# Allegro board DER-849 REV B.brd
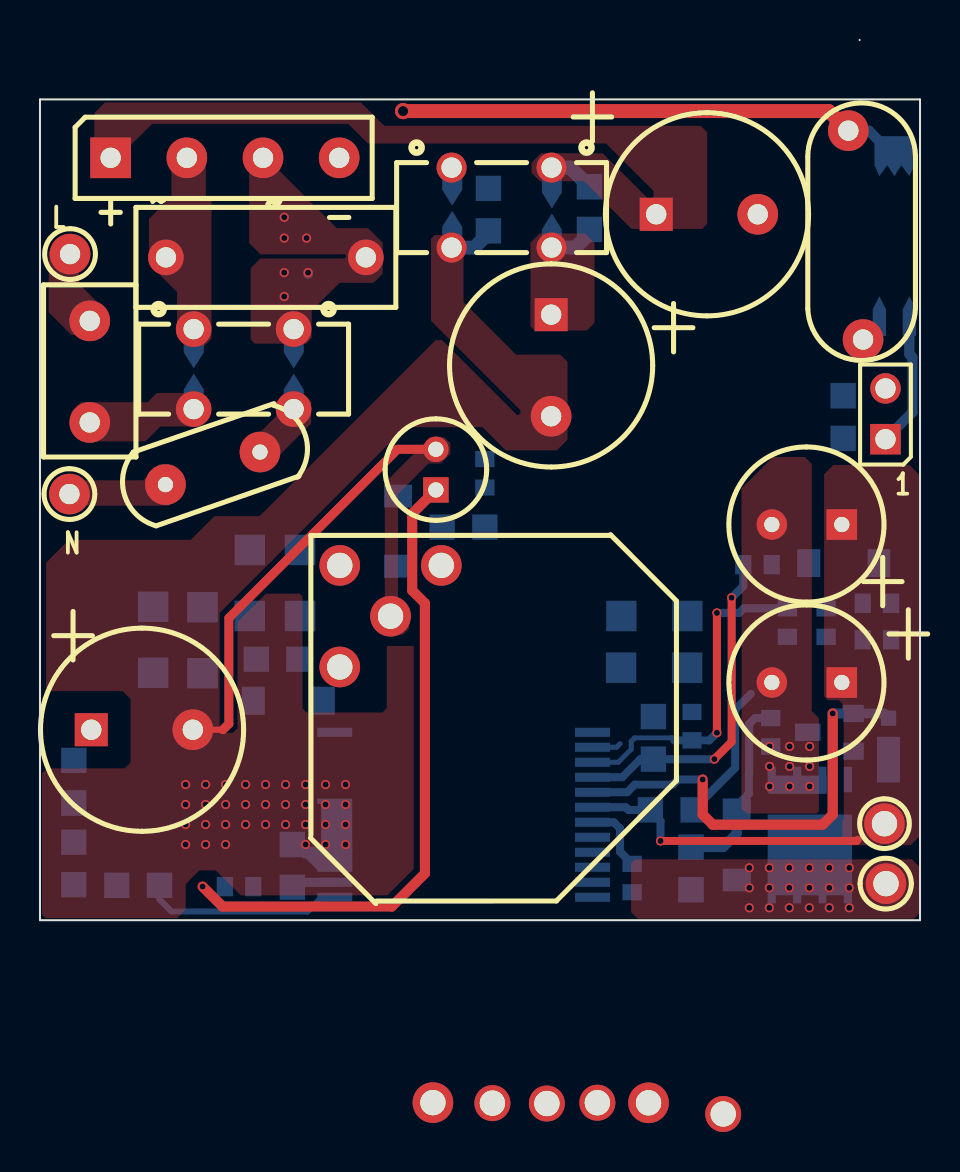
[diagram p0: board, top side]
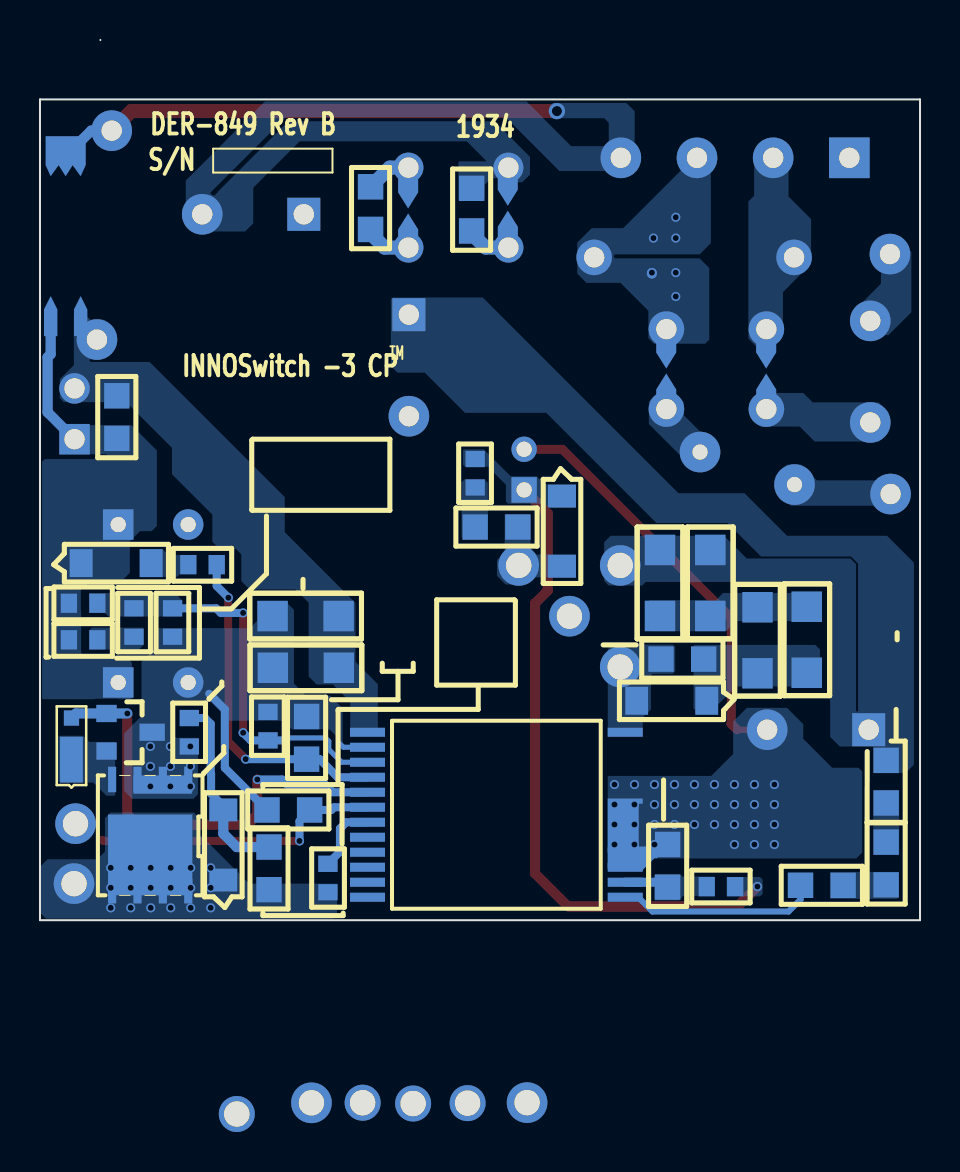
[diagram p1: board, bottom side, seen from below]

Outline 44.02 x 44.02 mm; copper layers: TOP, BOTTOM. Coordinates in mm from the lower left corner of the outline.
Outline path: 0,41.05 44.02,41.05 44.02,0 0,0 0,41.05

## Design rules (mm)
constraint set DEFAULT: min track width 0.508

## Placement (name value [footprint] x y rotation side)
BR1  KBP306G-BP  [PIDAXBRIDGEKBP306G]  3.54 38.13 0 top
C1  18 uf  [PIPOLCAPCYLD400LS200040]  30.82 35.3 0 top
C2  18 uf  [PIPOLCAPCYLD400LS200040]  25.57 30.28 270 top
C3  18 uf  [PIPOLCAPCYLD400LS200040]  2.57 9.53 0 top
C4  0.1 uF  [PINPXCAPRAD5X13X11P1MM040]  6.3 33.15 0 top
C5  2.2 nF  [PISMC1206]  13 18.52 270 bottom
C6  1 uF  [PISMC0805]  12.62 1.65 90 bottom
C7  100 pF  [PISMC0603]  22.25 23.06 270 bottom
C8  10 uF  [PIPOLCAPCLYD200LS80030]  19.8 21.52 90 top
C9  1 nF  [PISMC0603]  36.55 10.11 270 bottom
C10  2.2 uF  [PISMC0805]  30.68 10.19 270 bottom
C11  330 uF  [PIPOLCAPCYLD315LS138D030]  40.11 19.79 180 top
C12  330 uF  [PIPOLCAPCYLD315LS138D030]  40.11 11.89 180 top
C13  2.2 uF  [PISMC0805]  40.18 24.09 90 bottom
C14  330 pF  [PISMC0603]  32.61 10.41 270 bottom
C15  1 nF  [PINPYCAPRAD540X290LS400040]  42.93 39.04 260 top
C16  2.2 uF  [PISMC0805]  32.66 5.51 180 bottom
C17  47 pF  [PISMC0805]  10.82 13.06 0 bottom
C18  47 nF  [PISMC0603]  42.57 14.02 180 bottom
D1  S1ML  [PI_SM_SOD-123_12]  10.67 10.97 0 bottom
D2  S1ML  [PI_SM_SOD-123_12]  17.91 21.21 270 bottom
D3  S1ML  [PI_SM_SOD-123_12]  34.85 2.01 90 bottom
D5  PD3S140-7  [PISMD_POWERDI323]  42.44 8.03 270 bottom
F1  3.15 A  [PI_RST_MICROFUSE]  2.49 29.97 270 top
FL1  Hole_50mils  [PI_HOLE_50MIL]  42.24 4.83 0 top
FL2  Hole_50mils  [PI_HOLE_50MIL]  42.32 1.83 90 top
J1  OUTPUT  [PI_MOLEX_2_100_HEADER]  42.29 24.05 90 top
L1  700 uH  [PI_4P_10XD4MMD40]  10.19 27.56 90 top
L2  5000 uH  [PI_4P_10XD4MMD40]  23.09 35.64 90 top
NOREF  -  []  0 41.05 0 top
NOREF#2  -  []  -150.78 54.23 0 top
NOREF#3  -  []  0 0 90 top
NOREF#4  -  []  -228.6 -144.78 0 top
Q1  TSM160N10LCR  [PISMPQFN5X6B]  36.6 7.04 0 bottom
Q4  AO3415A  [PISMSOT23123_1]  40.69 8.46 270 bottom
R1  20  [PISMR1206]  5.66 15.68 270 bottom
R2  240 k  [PISMR1206]  10.49 18.52 270 bottom
R3  10  [PISMR0805]  22.25 19.66 180 bottom
R4  6.2 k  [PISMR0603]  9.25 1.68 0 bottom
R5  100  [PISMR0603]  36.6 17.78 180 bottom
R6  47  [PISMR0603]  29.62 1.4 90 bottom
R7  10  [PISMR0805]  32.56 1.52 90 bottom
R8  0.025  [PISMR1206]  32.37 12.62 180 bottom
R9  1.2 M  [PISMR0805]  1.69 7.99 270 bottom
R10  1.2 M  [PISMR0805]  1.69 3.9 270 bottom
R11  1.2 M  [PISMR0805]  3.84 1.74 0 bottom
R12  100 k  [PISMR0603]  42.57 15.85 180 bottom
R13  7.5 k  [PISMR0603]  37.39 15.6 270 bottom
R14  0.025  [PISMR1206]  32.38 15.21 180 bottom
R15  4.7 k  [PISMR0805]  27.48 36.68 270 bottom
R16  4.7 k  [PISMR0805]  22.43 36.6 270 bottom
R17  20  [PISMR1206]  8.13 15.65 270 bottom
R18  10.0K  [PISMR0603]  39.32 14.17 90 bottom
RT1  2.5  [PI_RAD150X300LS200D030]  11 23.41 199 top
SG1  6.0mm gap  [PI_SPARK_GAP_6P5MM_3P]  42.73 34.46 270 bottom
T1  RM7/I  [PI_BOBBIN_RM7_8P_CLP]  30.23 7.58 180 top
TP1  N  [PITPKEYSTONE100X100]  1.47 21.31 0 top
TP2  L  [PITPKEYSTONE100X100]  1.5 33.31 0 top
U1  INN3267C-H205  [PI_IC_INSOP_24D]  27.64 9.4 180 bottom
VR1  MMSZ5248B-7-F  [PI_SM_SOD-123_12]  41.96 17.86 180 bottom

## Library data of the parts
BR1 = DISCRETE BRIDGE_+~~-
C1-C3 = CAP POL: alternate symbols: (pipolcapclyd395x630ls200030h)
C4 = CAP NP: alternate symbols: (pinpxcaprad5x13x11p1mm040h)
C5-C7 C9 C10 C13 C16-C18 = CAP NP
C8 = CAP POL: alternate symbols: (pipolcapclyd200ls80030h)
C11 C12 = CAP POL: alternate symbols: (pipolcapcyld315ls138d030h)
C14 = CAP NP: alternate symbols: (pismc0603_1)
C15 = CAP NP: alternate symbols: (pinpycaprad540x290ls400040h,pinpycaprad500x220ls400040)
D1-D3 D5 = DIODE
F1 = FUSE: alternate symbols: (pirstmicrofusehoz)
FL1 FL2 = FlyingLead
J1 = CON2
L1 L2 = TORRID 4P_21_34
Q1 = FET_N_SGD_123_4_5678
Q4 = FET_P_GSD
R1-R5 R7-R18 = R
R6 = R: alternate symbols: (pismr0603_1)
RT1 = THERMISTOR: alternate symbols: (pirad400x300ls200040_h)
SG1 = SPARK_GAP_3p
T1 = BRM7_8P_CLP_2
TP1 TP2 = TESTPOINT
U1 = Inno3CP
VR1 = DIODE_ZENER

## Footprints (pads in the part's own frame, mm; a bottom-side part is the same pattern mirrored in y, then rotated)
PI_4P_10XD4MMD40
  round 1.5 hole 1.016: 1(-2,2.5) 2(2,2.5) 3(2,-2.5) 4(-2,-2.5)
PI_BOBBIN_RM7_8P_CLP
  round 1.8 hole 1.27: 1(2.355,16.71) 6(7.605,16.73) 7(-3.94,17.275) 8(4.88,16.75)
  round 2.032 hole 1.27: 2(10.16,-10.16) 3(12.7,-7.62) 4(15.24,-10.16) 5(15.24,-5.08) CLP1(-0.205,16.715) CLP2(10.58,16.705)
PI_HOLE_50MIL
  round 2.032 hole 1.27: 1(0,0)
PI_IC_INSOP_24D
  rect 1.75x0.45 smd: 1(0,0) 2(0,-0.75) 3(0,-1.5) 4(0,-2.25) 5(0,-3) 6(0,-3.75) 7(0,-4.5) 8(0,-5.25) 9(0,-6) 10(0,-6.75) 11(0,-7.5) 12(0,-8.25) 13(12.89,-8.25) 14(12.89,-7.5) 15(12.89,-6.75) 24(12.89,0)
  custom 0.438x0.438 smd: 16(12.89,-4.67)
PI_MOLEX_2_100_HEADER
  rect 1.524x1.524 hole 1.016: 1(0,0)
  round 1.524 hole 1.016: 2(2.54,0)
PI_RAD150X300LS200D030
  round 2.032 hole 0.762: 1(0,0) 2(5,0)
PI_RST_MICROFUSE
  round 2.032 hole 1.016: 1(0,0) 2(5.08,0)
PI_SM_SOD-123_12
  rect 1.143x1.397 smd: 1(0,0) 2(3.505,0)
PI_SPARK_GAP_6P5MM_3P
  custom 0.5x0.5 smd: 1(-3.75,0)
  custom 0.167x0.167 smd: 2(4.25,0.75) 3(4.25,-0.75)
PIDAXBRIDGEKBP306G
  rect 2.032x2.032 hole 1.016: 1(0,0)
  round 2.032 hole 1.016: 2(3.81,0) 3(7.62,0) 4(11.43,0)
PINPXCAPRAD5X13X11P1MM040
  round 1.778 hole 1.016: 1(0,0) 2(10,0)
PINPYCAPRAD540X290LS400040
  round 2.032 hole 1.016: 1(0,-2.54) 2(10.16,0)
PIPOLCAPCLYD200LS80030
  rect 1.27x1.27 hole 0.762: 1(0,0)
  round 1.27 hole 0.762: 2(2.032,0)
PIPOLCAPCYLD315LS138D030
  rect 1.524x1.524 hole 0.762: 1(0,0)
  round 1.524 hole 0.762: 2(3.5,0)
PIPOLCAPCYLD400LS200040
  rect 1.651x1.651 hole 1.016: 1(0,0)
  round 2.032 hole 1.016: 2(5.08,0)
PISMC0603
  rect 0.813x0.965 smd: 1(0,0) 2(1.422,0)
PISMC0805
  rect 1.27x1.27 smd: 1(0,0) 2(2.134,0)
PISMC1206
  rect 1.524x1.524 smd: 1(0,0) 2(3.302,0)
PISMD_POWERDI323
  rect 2.286x1.143 smd: 1(0,0)
  rect 0.762x0.762 smd: 2(-2.083,0)
PISMPQFN5X6B
  rect 0.406x1.27 smd: 1(0,0) 2(1.27,0) 3(2.54,0) 4(3.81,0)
  rect 0.406x1.219 smd: 5(3.81,5.588) 6(2.54,5.588) 7(1.27,5.588) 8(0,5.588)
PISMR0603
  rect 0.813x0.965 smd: 1(0,0) 2(1.422,0)
PISMR0805
  rect 1.27x1.27 smd: 1(0,0) 2(2.134,0)
PISMR1206
  rect 1.524x1.524 smd: 1(0,0) 2(3.302,0)
PISMSOT23123_1
  rect 0.864x1.016 smd: 1(-1.88,0) 2(0,0)
  rect 0.864x1.27 smd: 3(-0.94,2.286)
PITPKEYSTONE100X100
  round 2.032 hole 1.016: 1(0,0)

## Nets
18V, 1.67A: C11.1 C12.1 C13.1 C16.2 C18.1 FL1.1 J1.1 R12.1 SG1.3 U1.6 VR1.1
NC8: U1.8
NC9: U1.9
NC10: U1.10
NC11: U1.11
NC12: U1.12
NC15: U1.15
RTN: C13.2 C15.2 J1.2 R8.2 R14.2 SG1.2 U1.1
N12273366: F1.2 L1.1
N12273454: BR1.1 C1.1 L2.3 R15.1
N12273677: BR1.4 C1.2 C15.1 L2.2 R16.1 SG1.1
N12273859: C2.1 C3.1 C5.1 L2.4 R2.1 R9.1 R15.2 T1.4
N12273903: C2.2 C3.2 C6.2 C8.2 L2.1 R16.2 T1.3 U1.16
N12275039: C5.2 R1.1 R2.2 R17.1
N12275267: C6.1 R4.2 U1.14
N12275350: D2.2 R3.2 T1.2
N12275682: C7.2 R3.1
N12275686: C7.1 C8.1 D2.1 R4.1
N12279930: R6.2 U1.7
N12279938: D3.1 FL2.1 Q1.5 Q1.6 Q1.7 Q1.8 R6.1 R7.1
N12280045: C9.2 C10.1 C11.2 C12.2 C14.1 C16.1 Q1.1 Q1.2 Q1.3(S3) Q4.3 R8.1 R13.2 R14.1 U1.2
N12283028: R11.2 U1.13(VPIN)
N12284778: C14.2 R12.2 R13.1 R18.2 U1.3
N12285860: L1.4 RT1.1
N12290600: C9.1 D3.2 R7.2
N12292662: D5.1 Q1.4 Q4.2(S)
N12292685: D5.2 Q4.1 U1.5
N12293491: C10.2 R5.2 U1.4
N12296994: R5.1 VR1.2
N12297940: BR1.3(AC2) C4.2 L1.3
N12297952: BR1.2 C4.1 L1.2
N12298342: C17.1 D1.1 R1.2 R17.2
N12298360: C17.2 D1.2 T1.5 U1.24
N12331858: R9.2 R10.1
N12331878: R10.2 R11.1
N12332729: F1.1 TP2.1
N12332733: RT1.2 TP1.1
N123253661: C18.2 R18.1

Pads without a net: T1 1 6 7 8 CLP1 CLP2

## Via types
v1: diameter 0.457, hole 0.305, TOP to BOTTOM, 74 vias
v2: diameter 0.813, hole 0.508, TOP to BOTTOM, 1 via

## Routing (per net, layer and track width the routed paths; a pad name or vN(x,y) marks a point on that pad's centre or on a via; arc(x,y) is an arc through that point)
18V, 1.67A: length 21.4
  TOP w0.4: 40.89,4.01 40.84,3.96 v1(31.04,3.96)
  BOTTOM w0.4: v1(31.04,3.96) 31.04,4.95 30.53,5.46 C16.2 29.44,5.51 29.31,5.65 U1.6
  BOTTOM w0.508: J1.1 43.64,25.4 43.64,28.15 43.48,28.31 SG1.3
N12273454: length 2.3
  BOTTOM w0.7: R15.1 26.52,37.64 L2.3
N12273677: length 25.5
  TOP w0.7: C15.1 39.45,40.46 v2(18.16,40.46)
  BOTTOM w0.508: C15.1 41.46,39.48 SG1.1
N12273859: length 2.4
  BOTTOM w0.7: L2.4 26.78,33.64 27.48,34.34 R15.2
N12273903: length 23.3
  TOP w0.3: C3.2 9.15,9.53
  TOP w0.45: C8.2 17.89,23.55 9.45,15.11 9.45,9.82 9.15,9.53
  BOTTOM w0.7: R16.2 22.43,34.34 21.73,33.64 L2.1
  vias: v1(7.28,6.78) v1(7.28,5.78) v1(7.28,4.78) v1(7.28,3.78) v1(8.28,6.78) v1(8.28,5.78) v1(8.28,4.78) v1(8.28,3.78) v1(9.28,6.78) v1(9.28,5.78) v1(9.28,4.78) v1(9.28,3.78) v1(10.28,6.78) v1(10.28,5.78) v1(10.28,4.78) v1(11.28,6.78) v1(11.28,5.78) v1(11.28,4.78) v1(12.28,6.78) v1(12.28,5.78) v1(12.28,4.78) v1(13.28,6.78) v1(13.28,5.78) v1(13.28,4.78) v1(13.28,3.78) v1(14.28,6.78) v1(14.28,5.78) v1(14.28,4.78) v1(14.28,3.78) v1(15.28,6.78) v1(15.28,5.78) v1(15.28,4.78) v1(15.28,3.78)
N12275267: length 2.2
  BOTTOM w0.45: U1.14 12.87,1.9 C6.1
N12275686: length 32.2
  TOP w0.504: v1(8.13,1.68) 9.13,0.69 17.6,0.69 19.25,2.34 19.25,15.85 18.62,16.48 18.62,20.33 C8.1
N12279930: length 3.5
  BOTTOM w0.4: U1.7 28.7,4.9 29.02,4.58 29.02,3.42 R6.2
N12279938:
  vias: v1(35.48,2.62) v1(35.48,1.62) v1(35.48,0.62) v1(36.48,2.62) v1(36.48,1.62) v1(36.48,0.62) v1(37.48,2.62) v1(37.48,1.62) v1(37.48,0.62) v1(38.48,2.62) v1(38.48,1.62) v1(38.48,0.62) v1(39.48,2.62) v1(39.48,1.62) v1(39.48,0.62) v1(40.48,2.62) v1(40.48,1.62) v1(40.48,0.62)
N12280045: length 8.5
  BOTTOM w0.25: U1.2 28.84,8.65 29.02,8.82
  BOTTOM w0.4: C16.1 34.77,7.62 34.77,10.54 35.55,11.32
  vias: v1(36.5,8.69) v1(36.5,7.69) v1(36.5,6.69) v1(37.5,8.69) v1(37.5,7.69) v1(37.5,6.69) v1(38.5,8.69) v1(38.5,7.69) v1(38.5,6.69)
N12283028: length 10
  BOTTOM w0.3: R11.2 5.98,1.03 6.58,0.43 13.38,0.43 14.1,1.15 U1.13
N12284778: length 16.8
  TOP w0.4: v1(33.86,9.37) v1(33.86,15.37)
  BOTTOM w0.25: 31.73,8.99 31.6,9.12 29.74,9.12 29.57,8.95 29.57,8.54 28.93,7.9 U1.3
  BOTTOM w0.4: R13.1 35.2,15.6 34.98,15.37 v1(33.86,15.37) ; 31.73,8.99 C14.2 33.48,8.99 v1(33.86,9.37)
N12290600: length 9.5
  BOTTOM w0.4: D3.2 34.85,5.71 35.46,6.32 35.46,7.31 35.48,7.33 35.48,9.82 35.77,10.11 C9.1
  BOTTOM w0.508: R7.2 34.18,3.66 34.85,4.33 D3.2
N12292685: length 22.4
  TOP w0.508: v1(39.65,10.34) 39.65,5.28 39.14,4.78 33.66,4.78 33.15,5.28 v1(33.15,7.04)
  BOTTOM w0.4: v1(33.15,7.04) 31.91,7.04 31.65,6.78 29.76,6.78 29.37,6.4 U1.5
  BOTTOM w0.508: D5.2 42.21,10.34 Q4.1 v1(39.65,10.34)
N12293491: length 16.8
  TOP w0.4: v1(33.73,8.05) 34.59,8.92 v1(34.59,16.13)
  BOTTOM w0.4: v1(34.59,16.13) 35.18,16.71 35.18,17.78 ; U1.4 29.13,7.15 30.03,8.05 C10.2 v1(33.73,8.05)
N12297940: length 0
  BOTTOM w0.508: 13.41,32.33 13.41,32.36
  vias: v1(12.22,35.15) v1(12.22,34.11) v1(12.22,32.38) v1(12.22,31.19) v1(13.34,34.11) v1(13.41,32.38)

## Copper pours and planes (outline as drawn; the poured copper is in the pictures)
18V, 1.67A on TOP: 40.13,10.82 39.95,11 39.42,11 39.22,11.2 39.22,22.3 39.69,22.77 43.49,22.77 43.97,22.29 43.97,4.17 43.55,3.75 40.4,3.75 40.13,4.01
18V, 1.67A on BOTTOM: 39.42,11.1 39.42,12.88 39.71,13.17 41.77,13.17 41.96,13.36 41.96,15.47 41.97,15.48 41.97,16.5 41.43,17.04 39.85,17.04 39.52,17.37 39.52,18.95 39.01,19.46 38.43,19.46 38.18,19.71 38.18,23.5 39.44,24.75 42.98,24.75 42.98,23.55 42.74,23.31 42.73,23.3 40.69,23.3 40.62,23.23 40.62,23.12 40.69,23.06 43.79,23.06 43.91,22.93 43.91,11.07 43.89,11.05 39.47,11.05
RTN on BOTTOM: 33.95,16.95 33.95,18.3 34.34,18.69 35.17,18.69 35.4,18.92 35.4,20.28 37.41,22.3 37.41,23.62 37.82,24.03 37.83,24.03 37.83,24.04 39.7,25.91 42.82,25.91 43.03,26.11 43.03,27.05 42.32,27.76 42.32,30.37 42.27,30.43 41.89,30.43 41.49,30.03 40.79,30.03 40.28,29.51 40.28,28.57 40.77,28.09 41.45,28.09 41.55,27.99 41.48,27.91 38.53,27.91 31.78,21.16 31.78,19.41 28.23,15.86 28.23,12.92 27.12,11.8 27.12,9.25 28.35,9.25 28.5,9.4 28.5,10.92 29.36,11.79 30.18,11.79 30.58,12.19 30.58,15.88 31.23,16.53 33.53,16.53
N12273366 on BOTTOM (solid shape): 8.19,26.54 8.19,25.33 8.11,25.24 7.19,25.24 7.19,26.54 7.69,27.34
N12273366 on TOP: 5.28,23.95 6.02,24.69 7.98,24.69 8.43,25.15 8.43,25.98 8.05,26.37 5.84,26.37 5.38,25.91 2.06,25.91 1.59,25.44 1.59,24.41 2.05,23.95
N12273366 on BOTTOM: 5.27,23.94 6.02,24.69 7.98,24.69 8.43,25.15 8.43,25.98 8.05,26.37 5.84,26.37 5.37,25.9 2.07,25.9 1.57,25.4 1.57,24.41 2.04,23.94
N12273454 on BOTTOM (solid shape): 26.1,36.4 25.6,35.6 25.1,36.4 25.1,37.61 25.19,37.69 26.1,37.69
N12273454 on TOP: 5.61,39.83 15.42,39.83 16.41,38.84 28.32,38.84 30.68,36.47 30.68,36.17 30.58,36.07 30.43,36.07 28.14,38.35 25.07,38.35 24.59,37.87 24.59,37.36 24.99,36.96 27.2,36.96 29.59,34.57 33.12,34.57 33.38,34.82 33.38,39.4 33.05,39.73 17.22,39.73 16.05,40.89 3.25,40.89 2.72,40.36 2.72,37.44 2.92,37.24 4.06,37.24 4.37,37.54 4.37,38.58
N12273677 on BOTTOM (solid shape): 21.12,36.53 20.62,35.73 20.12,36.53 20.12,37.74 20.2,37.83 21.12,37.83
N12273677 on BOTTOM: 14.61,37.47 18.03,37.47 20.73,40.16 31.72,40.16 35.48,36.4 35.48,36.35 35.38,36.25 35.28,36.25 35.13,36.4 35.13,36.42 31.6,39.95 21.29,39.95 19.51,38.18 19.51,37.29 19.89,36.91 20.62,36.91 20.83,37.11 21.44,37.11 21.77,36.78 21.77,36.07 21.87,35.97 23.04,35.97 23.09,36.02 23.09,37.9 23.04,37.95 21.72,37.95 21.69,37.97 22.67,38.95 31.03,38.95 33.35,36.63 33.35,34.85 33.76,34.44 36.27,34.44 36.73,34.9 36.73,36.98 32.77,40.94 19.68,40.94 17.45,38.71 15.7,38.71 15.57,38.84 15.57,39.88 15.8,40.11 18.44,40.11 18.52,40.18 18.52,40.72 18.36,40.87 14.68,40.87 14.27,40.46 14.27,37.8
N12273859 on BOTTOM (solid shape): 26.1,34.54 26.1,33.33 26.02,33.25 25.1,33.25 25.1,34.54 25.6,35.34
N12273859 on TOP: 24.99,34.34 24.54,33.88 24.54,29.69 24.74,29.49 27.36,29.49 27.74,29.87 27.74,33.86 27.25,34.34
N12273859 on BOTTOM: 1.65,19.23 6.65,19.23 8.78,21.35 12.08,21.35 21.87,31.14 26.39,31.14 26.47,31.06 26.47,27.71 26.14,27.38 24.77,27.38 22.76,25.37 18.69,25.37 13.18,19.86 9.63,19.86 7.95,18.19 3.45,18.19 3.1,17.83 3.1,10.46 3.12,10.44 3.17,10.44 3.2,10.46 3.2,17.81 3.48,18.08 8.66,18.08 9.8,19.23 15.47,19.23 15.8,18.9 15.8,16.97 15.57,16.74 13.89,16.74 13.72,16.92 4.72,16.92 4.5,16.69 4.5,9.17 4.01,8.69 2.39,8.69 2.34,8.64 2.34,7.39 2.31,7.37 0.71,7.37 0.3,7.77 0.3,17.88
N12273903 on BOTTOM (solid shape): 21.12,34.68 21.12,33.47 21.03,33.38 20.12,33.38 20.12,34.68 20.62,35.48
N12273903 on BOTTOM (solid shape): 15.62,3.63 15.62,2.59 15.49,2.46 13.92,2.46 13.28,3.1 13.16,3.1 13.08,3.17 13.08,3.61 13.16,3.68 15.57,3.68
N12273903 on TOP: 0.28,0.1 0.1,0.28 0.1,7.34 0.36,7.59 4.24,7.59 4.52,7.87 4.52,11.07 4.14,11.46 0.48,11.46 0.3,11.63 0.3,17.88 1.45,19.02 7.54,19.02 8.72,20.21 10.99,20.21 19.79,29.01 20.12,29.01 23.85,25.27 23.95,25.27 24.03,25.35 24.03,25.5 19.56,29.97 19.56,34.09 19.74,34.26 20.62,34.26 21.18,33.71 21.18,30.91 23.81,28.28 26.02,28.28 26.39,27.91 26.39,24.03 25.86,23.5 23.29,23.5 22.14,24.65 18.28,24.65 8.99,15.37 8.99,9.6 9.22,9.37 9.65,9.37 9.88,9.6 9.88,14.91 11.3,16.33 12.98,16.33 13.13,16.18 13.13,10.59 13.34,10.39 17.12,10.39 17.35,10.62 17.35,13.67 17.4,13.72 18.67,13.72 18.69,13.69 18.69,2.54 17.3,1.14 10.13,1.14 8.79,2.49 7.98,2.49 7.29,1.8 7.29,0.53 6.86,0.1
N12273903 on TOP: 17.14,14.27 18.16,14.27 18.47,14.58 18.47,15.54 17.91,16.1 17.91,21.31 19.43,22.83 20.04,22.83 20.52,23.32 20.52,23.85 20.22,24.16 19.53,24.16 17.25,21.87 17.25,15.95 16.89,15.6 16.89,14.53
N12273903 on BOTTOM: 3.19,3.09 2.9,3.38 2.9,7.44 3.07,7.62 4.39,7.62 5.84,9.07 5.84,9.8 6.65,10.62 8.66,10.62 9.35,9.93 9.35,8.31 10.44,7.21 15.6,7.21 15.62,7.19 15.62,3.4 13.67,3.4 13.35,3.09
N12275039 on BOTTOM: 10.21,16 13.54,16 13.59,15.95 13.59,14.53 13.51,14.45 9.7,14.45 9.19,14.96 5.11,14.96 5,15.06 5,16.36 9.86,16.36
N12275267 on BOTTOM: 10.29,2.18 11.89,2.18 11.99,2.29 13.26,2.29 13.31,2.24 13.31,1.07 13.23,0.99 12.06,0.99 11.84,1.22 10.29,1.22
N12275350 on BOTTOM: 19.48,20.29 20.75,20.29 20.78,20.27 20.78,18.39 21.16,18.01 21.16,17.22 20.73,16.79 19.79,16.79 19.43,17.14 17.22,17.14 17.22,18.26 17.25,18.29 19.38,18.29 19.48,18.39
N12275682 on BOTTOM: 21.79,22.05 22.78,22.05 22.94,21.89 22.94,19.15 22.83,19.05 21.64,19.05 21.62,19.08 21.62,21.87
N12275686 on BOTTOM: 17.22,21.79 18.77,21.79 19.18,22.2 20.47,22.2 21.82,23.55 22.81,23.55 22.86,23.5 22.86,22.78 22.76,22.68 21.62,22.68 20.71,21.78 20.71,20.94 20.6,20.83 18.8,20.83 18.59,20.62 17.25,20.62 17.22,20.65
N12275686 on BOTTOM: 8,2.16 9.65,2.16 9.68,2.13 9.68,1.22 9.65,1.19 8,1.19 7.87,1.32 7.87,2.03
N12279938 on BOTTOM (solid shape): 40.61,1.24 36.4,1.24 36.4,5.28 40.61,5.28
N12279938 on TOP: 43.61,3.05 29.77,3.05 29.57,2.84 29.57,0.41 29.9,0.08 43.71,0.08 43.97,0.33 43.97,2.69
N12279938 on BOTTOM: 29.16,1.83 33.55,1.83 36.07,4.34 36.07,5.13 36.32,5.38 40.49,5.38 40.77,5.11 40.77,3.43 41.15,3.05 43.64,3.05 43.97,2.72 43.97,0.33 43.71,0.08 29.31,0.08 29.16,0.23
N12280045 on BOTTOM (solid shape): 39.34,6.32 36.42,6.32 36.42,7.24 39.34,7.24
N12280045 on TOP: 36.66,23.16 35.09,21.59 35.09,5.58 35.33,5.33 38.84,5.33 38.96,5.46 38.96,10.11 38.58,10.49 38.61,10.52 38.61,22.81 38.25,23.16
N12280045 on BOTTOM: 36.12,9.02 36.12,6.3 36.35,6.07 39.42,6.07 39.8,6.45 39.8,9.35 38.94,10.21 38.94,12.93 38.34,13.53 38.34,14.44 38.18,14.61 33.51,14.61 33.14,14.98 33.14,15.75 32.94,15.95 31.74,15.95 31.32,15.53 31.32,11.84 30.71,11.23 29.51,11.23 28.88,10.59 28.88,8.81 29.06,8.81 29.16,8.92 29.16,9.17 29.49,9.5 31.37,9.5 31.85,9.98 34.85,9.98 34.9,10.03 34.9,10.34 35.56,11 37.19,11 37.44,10.74 37.44,9.35 37.21,9.12 36.22,9.12
N12284778 on BOTTOM: 41.53,16.36 37.26,16.36 36.91,16 36.91,15.19 40.59,15.19 40.79,15.39 41.55,15.39 41.55,16.33
N12285860 on BOTTOM (solid shape): 13.19,26.54 13.19,25.33 13.11,25.24 12.19,25.24 12.19,26.54 12.69,27.34
N12285860 on TOP: 13.56,24.84 13.56,25.93 13.18,26.31 12.22,26.31 11.81,25.91 11.81,25.2 10.34,23.72 10.34,23.06 10.69,22.71 11.43,22.71
N12285860 on BOTTOM: 13.56,24.82 13.56,25.93 13.18,26.31 12.22,26.31 11.81,25.91 11.81,25.25 10.34,23.77 10.34,23.06 10.69,22.71 11.46,22.71
N12292662 on BOTTOM: 40.31,8.92 41.55,8.92 41.86,9.22 43.05,9.22 43.1,9.17 43.1,6.96 43.03,6.88 41.35,6.88 40.69,6.22 40.28,6.22 40.26,6.25 40.26,8.86
N12296994 on BOTTOM: 36.2,18.26 37.59,18.26 37.9,18.57 39.04,18.57 39.04,17.17 37.16,17.17 37.01,17.32 36.2,17.32
N12297940 on BOTTOM (solid shape): 13.19,28.39 12.69,27.59 12.19,28.39 12.19,29.6 12.28,29.69 13.19,29.69
N12297940 on TOP, BOTTOM: 10.46,38.51 10.46,33.86 11.02,33.3 15.24,33.3 15.32,33.22 15.32,33.17 15.24,33.1 11.02,33.1 10.54,32.61 10.54,29.03 10.74,28.83 13.31,28.83 13.59,29.11 13.59,30.48 14.99,31.88 16.69,31.88 17.14,32.33 17.14,33.88 16.42,34.61 14.85,34.61 11.98,37.48 11.98,38.37 11.58,38.76 10.72,38.76
N12297952 on BOTTOM (solid shape): 8.19,28.39 7.69,27.59 7.19,28.39 7.19,29.6 7.28,29.69 8.19,29.69
N12297952 on TOP, BOTTOM: 5.45,32.82 5.45,35.06 6.58,36.2 6.58,38.53 7.04,38.99 7.57,38.99 8.29,38.27 8.29,36.32 8.3,36.32 8.3,36.23 8.59,35.94 8.59,29.08 8.2,28.7 7.42,28.7 6.86,29.26 6.86,31.41
N12298342 on BOTTOM: 5,11.76 5.08,11.68 9.19,11.68 10.46,10.41 10.46,10.39 11.13,10.39 11.33,10.59 11.33,13.72 11.28,13.77 5.23,13.77 5,13.54
N12298360 on BOTTOM: 13.87,9.17 13.87,10.13 13.46,10.54 13.46,12.24 13.39,12.32 12.37,12.32 12.24,12.45 12.24,13.67 12.36,13.78 15.38,13.78 15.62,13.54 15.62,9.17
N12331858 on BOTTOM: 1.07,6.5 2.34,6.5 2.34,3.3 2.31,3.28 1.04,3.28 1.04,6.48
N12331878 on BOTTOM: 1.07,2.41 4.47,2.41 4.5,2.39 4.5,1.09 4.47,1.07 1.14,1.07 1.07,1.14
N12332729 on TOP: 0.64,33.63 1.7,33.63 1.96,33.38 1.96,31.83 3.35,30.43 3.35,29.64 2.97,29.26 1.57,29.26 0.43,30.4 0.43,33.43
N12332729 on BOTTOM: 0.43,33.43 0.43,30.4 1.57,29.26 2.97,29.26 3.35,29.64 3.35,30.43 1.96,31.83 1.96,33.38 1.7,33.63 0.64,33.63
N12332733 on TOP, BOTTOM: 0.66,21.72 0.66,21.06 0.99,20.73 6.45,20.73 7.21,21.49 7.21,22.23 6.65,22.78 5.94,22.78 5.16,22 0.94,22
N123253661 on BOTTOM: 38.84,14.63 41.43,14.63 41.55,14.5 41.55,13.54 39.07,13.54 38.84,13.77

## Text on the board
Ref Des/Silkscreen Bottom: TM | 1934 | INNOSwitch -3 CP | DER-849 Rev B | S/N
Ref Des/Silkscreen Top: L | N
User.6: 14.  FAB HOUSE LOGO,DATE CODE TO BE IN SILK SCREEN ONLY.DO NOT USE COPPER. | 13.  MATERIAL FR4 COPPER 2oz THICKNESS 0.062"
User.9: FIGURE | FINISHED_SIZE | 12.0 | 20.0 | 30.0 | 40.0 | 50.0 | DRILL CHART: TOP to BOTTOM | ALL UNITS ARE IN MILS | PLATED | QTY | 74 | 1 | 8 | 28 | 12
